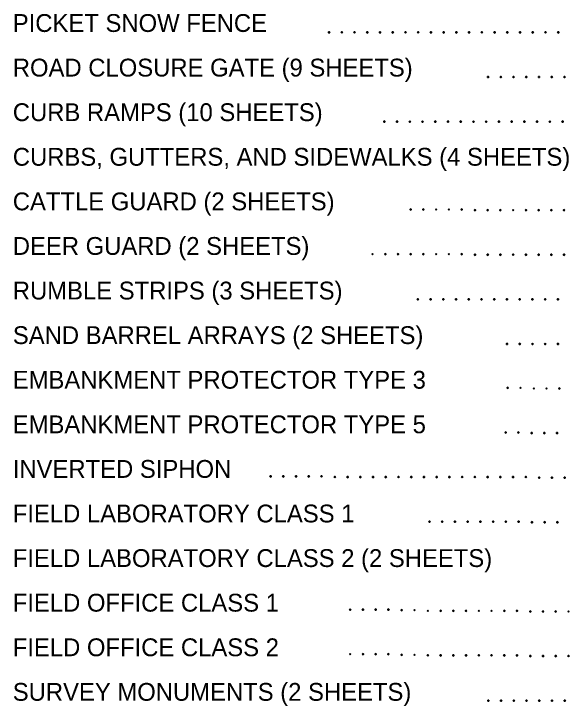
# Model space of a CAD drawing. Extents: x 0 to 1.42, y 0 to 0.92.
# Drawn here: x 0.6147 to 0.7964, y 0.4637 to 0.6903 of the extents above; entities that cross this region are included whole.
import ezdxf

# ---------------------------------------------------------------- set-up
doc = ezdxf.new("R2010")
doc.units = 0
doc.layers.add('DRAFT_Text-Notes', color=7, linetype='Continuous')

msp = doc.modelspace()

# ---------------------------------------------------------------- linework, layer by layer
at = {"layer": 'DRAFT_Text-Notes'}
for centre in [(0.71786, 0.68418), (0.72203, 0.68418), (0.72619, 0.68418), (0.73036, 0.68418), (0.73453, 0.68418), (0.73869, 0.68418), (0.74286, 0.68418), (0.74703, 0.68418), (0.75119, 0.68418), (0.75536, 0.68418), (0.75953, 0.68418), (0.76369, 0.68418), (0.76786, 0.68418), (0.77203, 0.68418), (0.77619, 0.68418), (0.78036, 0.68418), (0.78453, 0.68418), (0.78869, 0.68418), (0.79286, 0.68418), (0.7699, 0.66959), (0.77406, 0.66959), (0.77823, 0.66959), (0.7824, 0.66959), (0.78656, 0.66959), (0.79073, 0.66959), (0.7949, 0.66959), (0.73595, 0.65499), (0.74012, 0.65499), (0.74429, 0.65499), (0.74845, 0.65499), (0.75262, 0.65499), (0.75679, 0.65499), (0.76095, 0.65499), (0.76512, 0.65499), (0.76929, 0.65499), (0.77345, 0.65499), (0.77762, 0.65499), (0.78179, 0.65499), (0.78595, 0.65499), (0.79012, 0.65499), (0.79429, 0.65499), (0.74457, 0.62623), (0.74874, 0.62623), (0.7529, 0.62623), (0.75707, 0.62623), (0.76124, 0.62623), (0.76561, 0.62602), (0.76978, 0.62602), (0.77395, 0.62602), (0.77811, 0.62602), (0.77811, 0.62602), (0.78228, 0.62602), (0.78228, 0.62602), (0.78645, 0.62602), (0.79061, 0.62602), (0.79478, 0.62602), (0.73207, 0.61163), (0.73624, 0.61163), (0.7404, 0.61163), (0.74457, 0.61163), (0.74874, 0.61163), (0.7529, 0.61163), (0.75707, 0.61163), (0.76124, 0.61163), (0.76561, 0.61143), (0.76978, 0.61143), (0.77395, 0.61143), (0.77811, 0.61143), (0.77811, 0.61143), (0.78228, 0.61143), (0.78228, 0.61143), (0.78645, 0.61143), (0.79061, 0.61143), (0.79478, 0.61143), (0.74692, 0.59683), (0.75108, 0.59683), (0.75525, 0.59683), (0.75525, 0.59683), (0.75942, 0.59683), (0.75942, 0.59683), (0.76358, 0.59683), (0.76775, 0.59683), (0.77192, 0.59683), (0.77608, 0.59683), (0.77608, 0.59683), (0.78025, 0.59683), (0.78025, 0.59683), (0.78442, 0.59683), (0.78858, 0.59683), (0.79275, 0.59683), (0.7761, 0.58224), (0.7761, 0.58224), (0.78027, 0.58224), (0.78027, 0.58224), (0.78443, 0.58224), (0.7886, 0.58224), (0.79277, 0.58224), (0.77634, 0.56786), (0.7805, 0.56786), (0.78488, 0.56765), (0.78904, 0.56765), (0.79321, 0.56765), (0.77562, 0.55327), (0.77978, 0.55327), (0.78416, 0.55306), (0.78832, 0.55306), (0.79249, 0.55306), (0.69871, 0.53888), (0.70287, 0.53888), (0.70704, 0.53888), (0.71121, 0.53888), (0.71537, 0.53888), (0.71975, 0.53867), (0.72391, 0.53867), (0.72808, 0.53867), (0.73225, 0.53867), (0.73225, 0.53867), (0.73641, 0.53867), (0.73641, 0.53867), (0.74058, 0.53867), (0.74475, 0.53867), (0.74891, 0.53867), (0.75308, 0.53867), (0.75725, 0.53867), (0.76141, 0.53867), (0.76558, 0.53867), (0.76975, 0.53867), (0.77391, 0.53867), (0.77808, 0.53867), (0.78225, 0.53867), (0.78662, 0.53847), (0.79079, 0.53847), (0.79496, 0.53847), (0.75072, 0.52408), (0.75488, 0.52408), (0.75905, 0.52408), (0.76322, 0.52408), (0.76738, 0.52408), (0.77155, 0.52408), (0.77572, 0.52408), (0.77988, 0.52408), (0.78426, 0.52387), (0.78842, 0.52387), (0.79259, 0.52387), (0.72477, 0.49531), (0.72894, 0.49531), (0.73311, 0.49531), (0.73727, 0.49531), (0.74165, 0.49511), (0.74581, 0.49511), (0.75019, 0.4949), (0.75436, 0.4949), (0.75852, 0.4949), (0.76269, 0.4949), (0.76686, 0.4949), (0.77102, 0.4949), (0.77519, 0.4949), (0.77936, 0.4949), (0.78373, 0.49469), (0.7879, 0.49469), (0.79206, 0.49469), (0.79623, 0.49469), (0.79623, 0.49469), (0.72477, 0.48072), (0.72894, 0.48072), (0.73311, 0.48072), (0.73727, 0.48072), (0.74165, 0.48051), (0.74581, 0.48051), (0.75019, 0.48031), (0.75436, 0.48031), (0.75852, 0.48031), (0.76269, 0.48031), (0.76686, 0.48031), (0.77102, 0.48031), (0.77519, 0.48031), (0.77936, 0.48031), (0.78373, 0.4801), (0.7879, 0.4801), (0.79206, 0.4801), (0.79623, 0.4801), (0.79623, 0.4801), (0.76999, 0.4655), (0.77415, 0.4655), (0.77415, 0.4655), (0.77832, 0.4655), (0.77832, 0.4655), (0.78249, 0.4655), (0.78665, 0.4655), (0.79082, 0.4655), (0.79499, 0.4655)]:
    msp.add_circle(centre, 0.000208, dxfattribs=at)
for centre, start, end in [((0.71786, 0.68418), 0, 180), ((0.72203, 0.68418), 0, 180), ((0.72619, 0.68418), 0, 180), ((0.73036, 0.68418), 0, 180), ((0.73453, 0.68418), 0, 180), ((0.73869, 0.68418), 0, 180), ((0.74286, 0.68418), 0, 180), ((0.74703, 0.68418), 0, 180), ((0.75119, 0.68418), 0, 180), ((0.75536, 0.68418), 0, 180), ((0.75953, 0.68418), 0, 180), ((0.76369, 0.68418), 0, 180), ((0.76786, 0.68418), 0, 180), ((0.77203, 0.68418), 0, 180), ((0.77619, 0.68418), 0, 180), ((0.78036, 0.68418), 0, 180), ((0.78453, 0.68418), 0, 180), ((0.78869, 0.68418), 0, 180), ((0.79286, 0.68418), 0, 180), ((0.71786, 0.68418), 180, 0), ((0.72203, 0.68418), 180, 0), ((0.72619, 0.68418), 180, 0), ((0.73036, 0.68418), 180, 0), ((0.73453, 0.68418), 180, 0), ((0.73869, 0.68418), 180, 0), ((0.74286, 0.68418), 180, 0), ((0.74703, 0.68418), 180, 0), ((0.75119, 0.68418), 180, 0), ((0.75536, 0.68418), 180, 0), ((0.75953, 0.68418), 180, 0), ((0.76369, 0.68418), 180, 0), ((0.76786, 0.68418), 180, 0), ((0.77203, 0.68418), 180, 0), ((0.77619, 0.68418), 180, 0), ((0.78036, 0.68418), 180, 0), ((0.78453, 0.68418), 180, 0), ((0.78869, 0.68418), 180, 0), ((0.79286, 0.68418), 180, 0), ((0.7699, 0.66959), 0, 180), ((0.7699, 0.66959), 180, 0), ((0.77406, 0.66959), 0, 180), ((0.77406, 0.66959), 180, 0), ((0.77823, 0.66959), 0, 180), ((0.77823, 0.66959), 180, 0), ((0.7824, 0.66959), 0, 180), ((0.7824, 0.66959), 180, 0), ((0.78656, 0.66959), 0, 180), ((0.78656, 0.66959), 180, 0), ((0.79073, 0.66959), 0, 180), ((0.79073, 0.66959), 180, 0), ((0.7949, 0.66959), 0, 180), ((0.7949, 0.66959), 180, 0), ((0.73595, 0.65499), 0, 180), ((0.73595, 0.65499), 180, 0), ((0.74012, 0.65499), 0, 180), ((0.74012, 0.65499), 180, 0), ((0.74429, 0.65499), 0, 180), ((0.74429, 0.65499), 180, 0), ((0.74845, 0.65499), 0, 180), ((0.74845, 0.65499), 180, 0), ((0.75262, 0.65499), 0, 180), ((0.75262, 0.65499), 180, 0), ((0.75679, 0.65499), 0, 180), ((0.75679, 0.65499), 180, 0), ((0.76095, 0.65499), 0, 180), ((0.76095, 0.65499), 180, 0), ((0.76512, 0.65499), 0, 180), ((0.76512, 0.65499), 180, 0), ((0.76929, 0.65499), 0, 180), ((0.76929, 0.65499), 180, 0), ((0.77345, 0.65499), 0, 180), ((0.77345, 0.65499), 180, 0), ((0.77762, 0.65499), 0, 180), ((0.77762, 0.65499), 180, 0), ((0.78179, 0.65499), 0, 180), ((0.78179, 0.65499), 180, 0), ((0.78595, 0.65499), 0, 180), ((0.78595, 0.65499), 180, 0), ((0.79012, 0.65499), 0, 180), ((0.79012, 0.65499), 180, 0), ((0.79429, 0.65499), 0, 180), ((0.79429, 0.65499), 180, 0), ((0.74457, 0.62623), 0, 180), ((0.74457, 0.62623), 180, 0), ((0.74874, 0.62623), 0, 180), ((0.74874, 0.62623), 180, 0), ((0.7529, 0.62623), 0, 180), ((0.7529, 0.62623), 180, 0), ((0.75707, 0.62623), 0, 180), ((0.75707, 0.62623), 180, 0), ((0.76124, 0.62623), 0, 180), ((0.76124, 0.62623), 180, 0), ((0.76561, 0.62602), 0, 180), ((0.76561, 0.62602), 180, 0), ((0.76978, 0.62602), 0, 180), ((0.76978, 0.62602), 180, 0), ((0.77395, 0.62602), 0, 180), ((0.77395, 0.62602), 180, 0), ((0.77811, 0.62602), 0, 180), ((0.77811, 0.62602), 0, 180), ((0.77811, 0.62602), 180, 0), ((0.77811, 0.62602), 180, 0), ((0.78228, 0.62602), 0, 180), ((0.78228, 0.62602), 0, 180), ((0.78228, 0.62602), 180, 0), ((0.78228, 0.62602), 180, 0), ((0.78645, 0.62602), 0, 180), ((0.78645, 0.62602), 180, 0), ((0.79061, 0.62602), 0, 180), ((0.79061, 0.62602), 180, 0), ((0.79478, 0.62602), 0, 180), ((0.79478, 0.62602), 180, 0), ((0.73207, 0.61163), 0, 180), ((0.73624, 0.61163), 0, 180), ((0.7404, 0.61163), 0, 180), ((0.74457, 0.61163), 0, 180), ((0.74874, 0.61163), 0, 180), ((0.7529, 0.61163), 0, 180), ((0.75707, 0.61163), 0, 180), ((0.76124, 0.61163), 0, 180), ((0.73207, 0.61163), 180, 0), ((0.73624, 0.61163), 180, 0), ((0.7404, 0.61163), 180, 0), ((0.74457, 0.61163), 180, 0), ((0.74874, 0.61163), 180, 0), ((0.7529, 0.61163), 180, 0), ((0.75707, 0.61163), 180, 0), ((0.76124, 0.61163), 180, 0), ((0.76561, 0.61143), 0, 180), ((0.76561, 0.61143), 180, 0), ((0.76978, 0.61143), 0, 180), ((0.76978, 0.61143), 180, 0), ((0.77395, 0.61143), 0, 180), ((0.77395, 0.61143), 180, 0), ((0.77811, 0.61143), 0, 180), ((0.77811, 0.61143), 0, 180), ((0.77811, 0.61143), 180, 0), ((0.77811, 0.61143), 180, 0), ((0.78228, 0.61143), 0, 180), ((0.78228, 0.61143), 0, 180), ((0.78228, 0.61143), 180, 0), ((0.78228, 0.61143), 180, 0), ((0.78645, 0.61143), 0, 180), ((0.78645, 0.61143), 180, 0), ((0.79061, 0.61143), 0, 180), ((0.79061, 0.61143), 180, 0), ((0.79478, 0.61143), 0, 180), ((0.79478, 0.61143), 180, 0), ((0.74692, 0.59683), 0, 180), ((0.74692, 0.59683), 180, 0), ((0.75108, 0.59683), 0, 180), ((0.75108, 0.59683), 180, 0), ((0.75525, 0.59683), 0, 180), ((0.75525, 0.59683), 0, 180), ((0.75525, 0.59683), 180, 0), ((0.75525, 0.59683), 180, 0), ((0.75942, 0.59683), 0, 180), ((0.75942, 0.59683), 0, 180), ((0.75942, 0.59683), 180, 0), ((0.75942, 0.59683), 180, 0), ((0.76358, 0.59683), 0, 180), ((0.76358, 0.59683), 180, 0), ((0.76775, 0.59683), 0, 180), ((0.76775, 0.59683), 180, 0), ((0.77192, 0.59683), 0, 180), ((0.77192, 0.59683), 180, 0), ((0.77608, 0.59683), 0, 180), ((0.77608, 0.59683), 0, 180), ((0.77608, 0.59683), 180, 0), ((0.77608, 0.59683), 180, 0), ((0.78025, 0.59683), 0, 180), ((0.78025, 0.59683), 0, 180), ((0.78025, 0.59683), 180, 0), ((0.78025, 0.59683), 180, 0), ((0.78442, 0.59683), 0, 180), ((0.78442, 0.59683), 180, 0), ((0.78858, 0.59683), 0, 180), ((0.78858, 0.59683), 180, 0), ((0.79275, 0.59683), 0, 180), ((0.79275, 0.59683), 180, 0), ((0.7761, 0.58224), 0, 180), ((0.7761, 0.58224), 0, 180), ((0.78027, 0.58224), 0, 180), ((0.78027, 0.58224), 0, 180), ((0.78443, 0.58224), 0, 180), ((0.7886, 0.58224), 0, 180), ((0.79277, 0.58224), 0, 180), ((0.7761, 0.58224), 180, 0), ((0.7761, 0.58224), 180, 0), ((0.78027, 0.58224), 180, 0), ((0.78027, 0.58224), 180, 0), ((0.78443, 0.58224), 180, 0), ((0.7886, 0.58224), 180, 0), ((0.79277, 0.58224), 180, 0), ((0.77634, 0.56786), 0, 180), ((0.77634, 0.56786), 180, 0), ((0.7805, 0.56786), 0, 180), ((0.7805, 0.56786), 180, 0), ((0.78488, 0.56765), 0, 180), ((0.78488, 0.56765), 180, 0), ((0.78904, 0.56765), 0, 180), ((0.78904, 0.56765), 180, 0), ((0.79321, 0.56765), 0, 180), ((0.79321, 0.56765), 180, 0), ((0.77562, 0.55327), 0, 180), ((0.77562, 0.55327), 180, 0), ((0.77978, 0.55327), 0, 180), ((0.77978, 0.55327), 180, 0), ((0.78416, 0.55306), 0, 180), ((0.78416, 0.55306), 180, 0), ((0.78832, 0.55306), 0, 180), ((0.78832, 0.55306), 180, 0), ((0.79249, 0.55306), 0, 180), ((0.79249, 0.55306), 180, 0), ((0.69871, 0.53888), 0, 180), ((0.69871, 0.53888), 180, 0), ((0.70287, 0.53888), 0, 180), ((0.70287, 0.53888), 180, 0), ((0.70704, 0.53888), 0, 180), ((0.70704, 0.53888), 180, 0), ((0.71121, 0.53888), 0, 180), ((0.71121, 0.53888), 180, 0), ((0.71537, 0.53888), 0, 180), ((0.71537, 0.53888), 180, 0), ((0.71975, 0.53867), 0, 180), ((0.71975, 0.53867), 180, 0), ((0.72391, 0.53867), 0, 180), ((0.72391, 0.53867), 180, 0), ((0.72808, 0.53867), 0, 180), ((0.72808, 0.53867), 180, 0), ((0.73225, 0.53867), 0, 180), ((0.73225, 0.53867), 0, 180), ((0.73225, 0.53867), 180, 0), ((0.73225, 0.53867), 180, 0), ((0.73641, 0.53867), 0, 180), ((0.73641, 0.53867), 0, 180), ((0.73641, 0.53867), 180, 0), ((0.73641, 0.53867), 180, 0), ((0.74058, 0.53867), 0, 180), ((0.74058, 0.53867), 180, 0), ((0.74475, 0.53867), 0, 180), ((0.74475, 0.53867), 180, 0), ((0.74891, 0.53867), 0, 180), ((0.74891, 0.53867), 180, 0), ((0.75308, 0.53867), 0, 180), ((0.75308, 0.53867), 180, 0), ((0.75725, 0.53867), 0, 180), ((0.75725, 0.53867), 180, 0), ((0.76141, 0.53867), 0, 180), ((0.76141, 0.53867), 180, 0), ((0.76558, 0.53867), 0, 180), ((0.76558, 0.53867), 180, 0), ((0.76975, 0.53867), 0, 180), ((0.76975, 0.53867), 180, 0), ((0.77391, 0.53867), 0, 180), ((0.77391, 0.53867), 180, 0), ((0.77808, 0.53867), 0, 180), ((0.77808, 0.53867), 180, 0), ((0.78225, 0.53867), 0, 180), ((0.78225, 0.53867), 180, 0), ((0.78662, 0.53847), 0, 180), ((0.78662, 0.53847), 180, 0), ((0.79079, 0.53847), 0, 180), ((0.79079, 0.53847), 180, 0), ((0.79496, 0.53847), 0, 180), ((0.79496, 0.53847), 180, 0), ((0.75072, 0.52408), 0, 180), ((0.75072, 0.52408), 180, 0), ((0.75488, 0.52408), 0, 180), ((0.75488, 0.52408), 180, 0), ((0.75905, 0.52408), 0, 180), ((0.75905, 0.52408), 180, 0), ((0.76322, 0.52408), 0, 180), ((0.76322, 0.52408), 180, 0), ((0.76738, 0.52408), 0, 180), ((0.76738, 0.52408), 180, 0), ((0.77155, 0.52408), 0, 180), ((0.77155, 0.52408), 180, 0), ((0.77572, 0.52408), 0, 180), ((0.77572, 0.52408), 180, 0), ((0.77988, 0.52408), 0, 180), ((0.77988, 0.52408), 180, 0), ((0.78426, 0.52387), 0, 180), ((0.78426, 0.52387), 180, 0), ((0.78842, 0.52387), 0, 180), ((0.78842, 0.52387), 180, 0), ((0.79259, 0.52387), 0, 180), ((0.79259, 0.52387), 180, 0), ((0.72477, 0.49531), 0, 180), ((0.72477, 0.49531), 180, 0), ((0.72894, 0.49531), 0, 180), ((0.72894, 0.49531), 180, 0), ((0.73311, 0.49531), 0, 180), ((0.73311, 0.49531), 180, 0), ((0.73727, 0.49531), 0, 180), ((0.73727, 0.49531), 180, 0), ((0.74165, 0.49511), 0, 180), ((0.74165, 0.49511), 180, 0), ((0.74581, 0.49511), 0, 180), ((0.74581, 0.49511), 180, 0), ((0.75019, 0.4949), 0, 180), ((0.75019, 0.4949), 180, 0), ((0.75436, 0.4949), 0, 180), ((0.75436, 0.4949), 180, 0), ((0.75852, 0.4949), 0, 180), ((0.75852, 0.4949), 180, 0), ((0.76269, 0.4949), 0, 180), ((0.76269, 0.4949), 180, 0), ((0.76686, 0.4949), 0, 180), ((0.76686, 0.4949), 180, 0), ((0.77102, 0.4949), 0, 180), ((0.77102, 0.4949), 180, 0), ((0.77519, 0.4949), 0, 180), ((0.77519, 0.4949), 180, 0), ((0.77936, 0.4949), 0, 180), ((0.77936, 0.4949), 180, 0), ((0.78373, 0.49469), 0, 180), ((0.78373, 0.49469), 180, 0), ((0.7879, 0.49469), 0, 180), ((0.7879, 0.49469), 180, 0), ((0.79206, 0.49469), 0, 180), ((0.79206, 0.49469), 180, 0), ((0.79623, 0.49469), 0, 180), ((0.79623, 0.49469), 0, 180), ((0.79623, 0.49469), 180, 0), ((0.79623, 0.49469), 180, 0), ((0.72477, 0.48072), 0, 180), ((0.72477, 0.48072), 180, 0), ((0.72894, 0.48072), 0, 180), ((0.72894, 0.48072), 180, 0), ((0.73311, 0.48072), 0, 180), ((0.73311, 0.48072), 180, 0), ((0.73727, 0.48072), 0, 180), ((0.73727, 0.48072), 180, 0), ((0.74165, 0.48051), 0, 180), ((0.74165, 0.48051), 180, 0), ((0.74581, 0.48051), 0, 180), ((0.74581, 0.48051), 180, 0), ((0.75019, 0.48031), 0, 180), ((0.75019, 0.48031), 180, 0), ((0.75436, 0.48031), 0, 180), ((0.75436, 0.48031), 180, 0), ((0.75852, 0.48031), 0, 180), ((0.75852, 0.48031), 180, 0), ((0.76269, 0.48031), 0, 180), ((0.76269, 0.48031), 180, 0), ((0.76686, 0.48031), 0, 180), ((0.76686, 0.48031), 180, 0), ((0.77102, 0.48031), 0, 180), ((0.77102, 0.48031), 180, 0), ((0.77519, 0.48031), 0, 180), ((0.77519, 0.48031), 180, 0), ((0.77936, 0.48031), 0, 180), ((0.77936, 0.48031), 180, 0), ((0.78373, 0.4801), 0, 180), ((0.7879, 0.4801), 0, 180), ((0.79206, 0.4801), 0, 180), ((0.79623, 0.4801), 0, 180), ((0.79623, 0.4801), 0, 180), ((0.78373, 0.4801), 180, 0), ((0.7879, 0.4801), 180, 0), ((0.79206, 0.4801), 180, 0), ((0.79623, 0.4801), 180, 0), ((0.79623, 0.4801), 180, 0), ((0.76999, 0.4655), 0, 180), ((0.76999, 0.4655), 180, 0), ((0.77415, 0.4655), 0, 180), ((0.77415, 0.4655), 0, 180), ((0.77415, 0.4655), 180, 0), ((0.77415, 0.4655), 180, 0), ((0.77832, 0.4655), 0, 180), ((0.77832, 0.4655), 0, 180), ((0.77832, 0.4655), 180, 0), ((0.77832, 0.4655), 180, 0), ((0.78249, 0.4655), 0, 180), ((0.78249, 0.4655), 180, 0), ((0.78665, 0.4655), 0, 180), ((0.78665, 0.4655), 180, 0), ((0.79082, 0.4655), 0, 180), ((0.79082, 0.4655), 180, 0), ((0.79499, 0.4655), 0, 180), ((0.79499, 0.4655), 180, 0)]:
    msp.add_arc(centre, 0.000208, start, end, dxfattribs=at)

# ---------------------------------------------------------------- texts
for s, p in [('PICKET SNOW FENCE', (0.61433, 0.68434)), ('ROAD CLOSURE GATE (9 SHEETS)', (0.61433, 0.66975)), ('CURB RAMPS (10 SHEETS)', (0.61433, 0.65516)), ('CURBS, GUTTERS, AND SIDEWALKS (4 SHEETS)', (0.61433, 0.64056)), ('CATTLE GUARD (2 SHEETS)', (0.61433, 0.62597)), ('DEER GUARD (2 SHEETS)', (0.61433, 0.61138)), ('RUMBLE STRIPS (3 SHEETS)', (0.61433, 0.59679)), ('SAND BARREL ARRAYS (2 SHEETS)', (0.61435, 0.5822)), ('EMBANKMENT PROTECTOR TYPE 3', (0.61432, 0.5676)), ('EMBANKMENT PROTECTOR TYPE 5', (0.61432, 0.55301)), ('INVERTED SIPHON', (0.61432, 0.53842)), ('FIELD LABORATORY CLASS 1', (0.61432, 0.52383)), ('FIELD LABORATORY CLASS 2 (2 SHEETS)', (0.61432, 0.50924)), ('FIELD OFFICE CLASS 1', (0.61432, 0.49464)), ('FIELD OFFICE CLASS 2', (0.61432, 0.48005)), ('SURVEY MONUMENTS (2 SHEETS)', (0.61432, 0.46546))]:
    msp.add_text(s, height=0.0058333, dxfattribs=at).set_placement(p)

doc.saveas('drawing.dxf')
